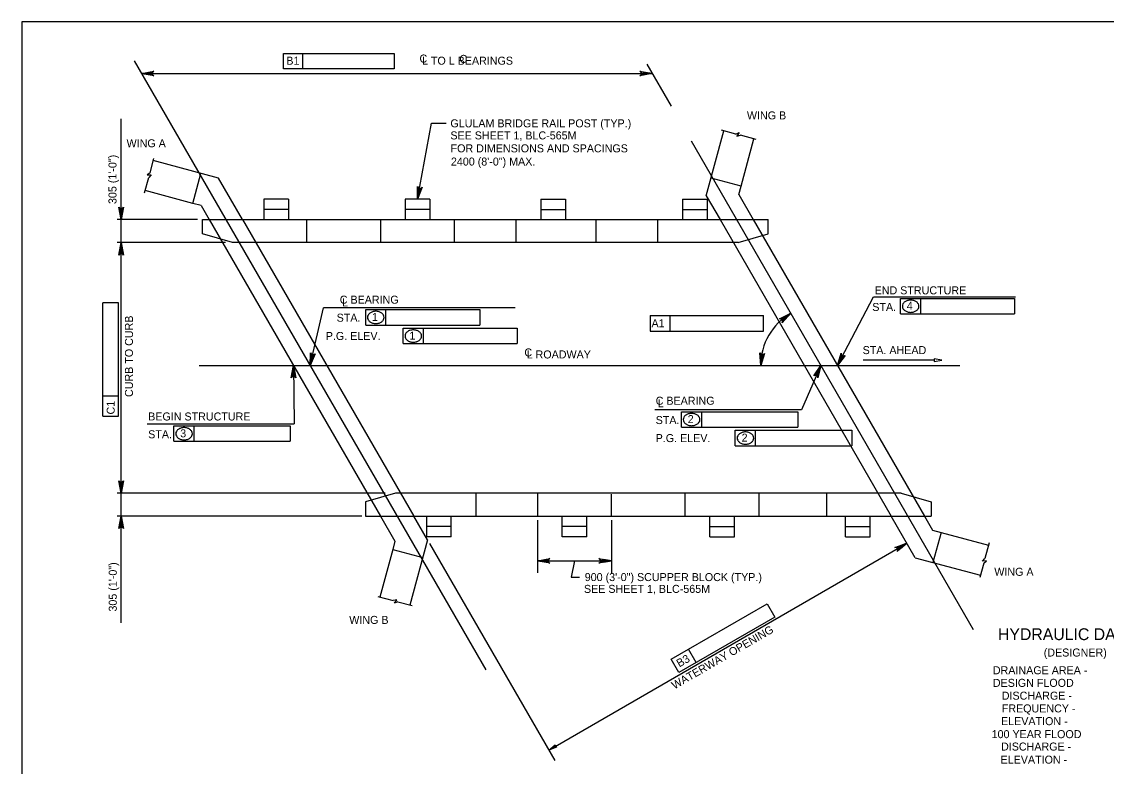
# Model space of a CAD drawing. Extents: x -8 to 75, y -110 to 0.
# Drawn here: x 1.75 to 18.01, y -55.91 to -44.75 of the extents above; entities that cross this region are included whole.
import ezdxf

# ---------------------------------------------------------------- set-up
doc = ezdxf.new("R2010")
doc.units = 0
for name, color, linetype in [('1', 7, 'Continuous'), ('2', 7, 'Continuous'), ('3', 7, 'Continuous'), ('4', 7, 'Continuous')]:
    doc.layers.add(name, color=color, linetype=linetype)

msp = doc.modelspace()

# ---------------------------------------------------------------- linework, layer by layer
at = {"layer": '1'}
msp.add_lwpolyline([(1.75, -65.25), (33.25, -65.25), (33.25, -44.75), (1.75, -44.75)], close=True, dxfattribs=at)
at = {"layer": '2'}
for p, q in [((12.012, -47.361), (12.274, -46.385)), ((12.533, -47.217), (12.723, -46.506)), ((4.699, -47.095), (3.723, -46.833)), ((4.314, -47.474), (4.435, -47.024)), ((5.059, -47.718), (4.699, -47.095)), ((12.533, -47.217), (12.083, -47.097)), ((4.314, -47.474), (3.602, -47.283)), ((12.499, -47.343), (12.533, -47.217)), ((5.747, -47.41), (5.378, -47.41)), ((5.378, -47.41), (5.378, -47.718)), ((5.747, -47.41), (5.747, -47.718)), ((7.869, -47.41), (7.5, -47.41)), ((7.5, -47.41), (7.5, -47.718)), ((7.869, -47.41), (7.869, -47.718)), ((9.531, -47.41), (9.9, -47.41)), ((9.531, -47.41), (9.531, -47.718)), ((9.9, -47.41), (9.9, -47.718)), ((11.654, -47.41), (12.023, -47.41)), ((11.654, -47.41), (11.654, -47.718)), ((12.012, -47.361), (12.218, -47.718)), ((12.023, -47.41), (12.023, -47.718)), ((12.499, -47.343), (12.715, -47.718)), ((4.44, -47.507), (4.314, -47.474)), ((4.44, -47.507), (4.561, -47.718)), ((4.461, -47.718), (12.938, -47.718)), ((4.461, -47.933), (4.461, -47.718)), ((4.561, -47.718), (7.129, -52.164)), ((5.059, -47.718), (7.626, -52.164)), ((12.218, -47.718), (14.785, -52.164)), ((12.715, -47.718), (15.282, -52.164)), ((12.938, -47.933), (12.938, -47.718)), ((4.908, -48.063), (4.461, -47.933)), ((12.49, -48.063), (12.938, -47.933)), ((12.49, -48.063), (4.908, -48.063)), ((7.351, -51.818), (6.904, -51.949)), ((14.933, -51.818), (7.351, -51.818)), ((14.933, -51.818), (15.381, -51.949)), ((6.904, -51.949), (6.904, -52.164)), ((15.381, -51.949), (15.381, -52.164)), ((6.904, -52.164), (15.381, -52.164)), ((7.129, -52.164), (7.345, -52.538)), ((7.832, -52.52), (7.626, -52.164)), ((7.821, -52.472), (7.821, -52.164)), ((8.19, -52.472), (8.19, -52.164)), ((9.851, -52.472), (9.851, -52.164)), ((10.22, -52.472), (10.22, -52.164)), ((12.067, -52.472), (12.067, -52.164)), ((12.436, -52.472), (12.436, -52.164)), ((14.097, -52.472), (14.097, -52.164)), ((14.466, -52.472), (14.466, -52.164)), ((15.145, -52.787), (14.785, -52.164)), ((15.282, -52.164), (15.404, -52.375)), ((8.19, -52.472), (7.821, -52.472)), ((10.22, -52.472), (9.851, -52.472)), ((12.067, -52.472), (12.436, -52.472)), ((14.097, -52.472), (14.466, -52.472)), ((15.404, -52.375), (15.53, -52.408)), ((15.53, -52.408), (15.409, -52.858)), ((15.53, -52.408), (16.241, -52.599)), ((7.311, -52.664), (7.12, -53.376)), ((7.345, -52.538), (7.311, -52.664)), ((7.311, -52.664), (7.761, -52.785)), ((7.832, -52.52), (7.57, -53.497)), ((15.145, -52.787), (16.121, -53.049))]:
    msp.add_line(p, q, dxfattribs=at)
at = {"layer": '3'}
for p, q in [((3.435, -45.336), (8.708, -54.47)), ((11.121, -45.387), (11.485, -46.018)), ((3.545, -45.527), (11.202, -45.527)), ((7.894, -46.272), (8.114, -46.272)), ((12.455, -46.434), (12.242, -46.377)), ((12.455, -46.434), (12.506, -46.413)), ((12.506, -46.413), (12.471, -46.465)), ((12.471, -46.465), (12.525, -46.453)), ((12.758, -46.515), (12.525, -46.453)), ((11.785, -46.537), (16.014, -53.863)), ((3.674, -47.015), (3.731, -46.801)), ((3.593, -47.318), (3.656, -47.084)), ((3.674, -47.015), (3.631, -47.048)), ((3.631, -47.048), (3.693, -47.044)), ((3.693, -47.044), (3.656, -47.084)), ((5.747, -47.564), (5.378, -47.564)), ((7.869, -47.564), (7.5, -47.564)), ((9.531, -47.564), (9.9, -47.564)), ((11.654, -47.564), (12.023, -47.564)), ((6.024, -48.063), (6.024, -47.718)), ((7.131, -48.063), (7.131, -47.718)), ((8.239, -48.063), (8.239, -47.718)), ((9.162, -48.063), (9.162, -47.718)), ((10.362, -48.063), (10.362, -47.718)), ((11.285, -48.063), (11.285, -47.718)), ((8.559, -51.818), (8.559, -52.164)), ((9.482, -51.818), (9.482, -52.164)), ((10.59, -52.164), (10.59, -51.835)), ((11.697, -52.164), (11.697, -51.818)), ((12.805, -52.164), (12.805, -51.818)), ((13.82, -52.164), (13.82, -51.818)), ((8.19, -52.318), (7.821, -52.318)), ((10.22, -52.318), (9.851, -52.318)), ((12.067, -52.318), (12.436, -52.318)), ((14.097, -52.318), (14.466, -52.318)), ((16.251, -52.564), (16.188, -52.798)), ((16.151, -52.838), (16.188, -52.798)), ((16.213, -52.834), (16.151, -52.838)), ((16.17, -52.867), (16.213, -52.834)), ((16.17, -52.867), (16.112, -53.081)), ((7.086, -53.367), (7.319, -53.429)), ((7.372, -53.417), (7.319, -53.429)), ((7.338, -53.469), (7.372, -53.417)), ((7.388, -53.448), (7.338, -53.469)), ((7.388, -53.448), (7.602, -53.505))]:
    msp.add_line(p, q, dxfattribs=at)
msp.add_lwpolyline([(3.663, -45.507), (3.663, -45.547), (3.545, -45.527)], close=True, dxfattribs=at)
at = {"layer": '4'}
for p, q in [((5.674, -45.225), (5.963, -45.225)), ((5.674, -45.456), (5.674, -45.225)), ((5.963, -45.456), (5.963, -45.225)), ((5.963, -45.225), (7.335, -45.225)), ((7.335, -45.225), (7.335, -45.456)), ((7.335, -45.456), (5.674, -45.456)), ((3.239, -53.763), (3.239, -46.209)), ((7.685, -47.41), (7.894, -46.272)), ((4.383, -47.718), (3.181, -47.718)), ((4.807, -48.063), (3.181, -48.063)), ((13.977, -49.903), (14.52, -48.874)), ((14.52, -48.874), (16.647, -48.874)), ((14.924, -48.899), (15.227, -48.899)), ((14.924, -49.129), (14.924, -48.899)), ((15.227, -49.129), (15.227, -48.899)), ((15.227, -48.899), (16.634, -48.899)), ((16.634, -48.899), (16.634, -49.129)), ((3.202, -48.965), (2.966, -48.965)), ((2.966, -50.363), (2.966, -48.965)), ((3.202, -50.666), (3.202, -48.965)), ((6.072, -49.903), (6.274, -49.042)), ((9.146, -49.042), (6.274, -49.042)), ((6.907, -49.067), (7.21, -49.067)), ((6.907, -49.298), (6.907, -49.067)), ((7.21, -49.298), (7.21, -49.067)), ((7.21, -49.067), (8.617, -49.067)), ((8.617, -49.067), (8.617, -49.298)), ((11.169, -49.154), (11.472, -49.154)), ((11.169, -49.154), (11.169, -49.39)), ((11.471, -49.39), (11.472, -49.154)), ((11.472, -49.154), (12.87, -49.154)), ((12.87, -49.39), (12.87, -49.154)), ((14.924, -49.129), (16.634, -49.129)), ((6.907, -49.298), (8.617, -49.298)), ((7.468, -49.346), (7.771, -49.346)), ((7.468, -49.576), (7.468, -49.346)), ((7.771, -49.576), (7.771, -49.346)), ((7.771, -49.346), (9.179, -49.346)), ((9.179, -49.346), (9.179, -49.576)), ((11.169, -49.39), (12.87, -49.39)), ((7.468, -49.576), (9.179, -49.576)), ((4.412, -49.903), (15.812, -49.903)), ((5.823, -49.903), (5.834, -50.78)), ((13.728, -49.903), (13.441, -50.567)), ((15.426, -49.825), (14.361, -49.825)), ((2.966, -50.665), (2.966, -50.363)), ((3.202, -50.363), (2.966, -50.363)), ((2.966, -50.665), (3.202, -50.666)), ((13.441, -50.567), (11.238, -50.567)), ((11.64, -50.597), (11.943, -50.597)), ((11.64, -50.828), (11.64, -50.597)), ((11.943, -50.828), (11.943, -50.597)), ((11.943, -50.597), (13.383, -50.597)), ((13.383, -50.597), (13.383, -50.828)), ((3.631, -50.78), (5.834, -50.78)), ((4.033, -51.041), (4.033, -50.81)), ((4.033, -50.81), (4.336, -50.81)), ((4.336, -51.041), (4.336, -50.81)), ((4.336, -50.81), (5.776, -50.81)), ((5.776, -50.81), (5.776, -51.041)), ((11.64, -50.828), (13.383, -50.828)), ((12.447, -51.107), (12.447, -50.876)), ((12.447, -50.876), (12.751, -50.876)), ((12.751, -51.107), (12.751, -50.876)), ((12.751, -50.876), (14.191, -50.876)), ((14.191, -50.876), (14.191, -51.107)), ((4.033, -51.041), (5.776, -51.041)), ((12.447, -51.107), (14.191, -51.107)), ((7.198, -51.818), (3.181, -51.818)), ((6.849, -52.164), (3.181, -52.164)), ((9.482, -52.226), (9.482, -53.011)), ((10.59, -52.226), (10.59, -53.011)), ((7.863, -52.575), (9.74, -55.825)), ((9.65, -55.67), (15.019, -52.57)), ((9.482, -52.834), (10.59, -52.834)), ((10.036, -52.834), (9.987, -53.08)), ((9.987, -53.08), (10.11, -53.08)), ((11.743, -54.159), (12.926, -53.478)), ((12.926, -53.478), (13.041, -53.678)), ((13.041, -53.678), (11.602, -54.507)), ((11.487, -54.307), (11.743, -54.159)), ((11.858, -54.359), (11.743, -54.159)), ((11.602, -54.507), (11.487, -54.307))]:
    msp.add_line(p, q, dxfattribs=at)
for points in [[(3.545, -45.527), (3.732, -45.492), (3.717, -45.502), (3.71, -45.515), (3.708, -45.527), (3.71, -45.54), (3.717, -45.552), (3.732, -45.562), (3.545, -45.527), (3.717, -45.552), (3.71, -45.54), (3.545, -45.527), (3.708, -45.527), (3.71, -45.515), (3.545, -45.527), (3.717, -45.502)], [(11.202, -45.527), (11.015, -45.562), (11.03, -45.552), (11.037, -45.54), (11.039, -45.527), (11.037, -45.515), (11.03, -45.502), (11.015, -45.492), (11.202, -45.527), (11.03, -45.502), (11.037, -45.515), (11.202, -45.527), (11.039, -45.527), (11.037, -45.54), (11.202, -45.527), (11.03, -45.552)], [(7.685, -47.41), (7.684, -47.22), (7.691, -47.236), (7.702, -47.246), (7.714, -47.25), (7.727, -47.25), (7.74, -47.245), (7.753, -47.233), (7.685, -47.41), (7.74, -47.245), (7.727, -47.25), (7.685, -47.41), (7.714, -47.25), (7.702, -47.246), (7.685, -47.41), (7.691, -47.236)], [(3.239, -47.718), (3.204, -47.531), (3.214, -47.545), (3.226, -47.553), (3.239, -47.555), (3.251, -47.553), (3.264, -47.545), (3.274, -47.531), (3.239, -47.718), (3.264, -47.545), (3.251, -47.553), (3.239, -47.718), (3.239, -47.555), (3.226, -47.553), (3.239, -47.718), (3.214, -47.545)], [(3.239, -48.063), (3.274, -48.25), (3.264, -48.236), (3.251, -48.228), (3.239, -48.226), (3.226, -48.228), (3.214, -48.236), (3.204, -48.25), (3.239, -48.063), (3.214, -48.236), (3.226, -48.228), (3.239, -48.063), (3.239, -48.226), (3.251, -48.228), (3.239, -48.063), (3.264, -48.236)], [(13.277, -49.122), (13.15, -49.263), (13.156, -49.246), (13.154, -49.232), (13.148, -49.221), (13.139, -49.212), (13.125, -49.207), (13.108, -49.207), (13.277, -49.122), (13.125, -49.207), (13.139, -49.212), (13.277, -49.122), (13.148, -49.221), (13.154, -49.232), (13.277, -49.122), (13.156, -49.246)], [(6.072, -49.903), (6.08, -49.713), (6.087, -49.73), (6.097, -49.74), (6.109, -49.745), (6.122, -49.745), (6.135, -49.741), (6.148, -49.729), (6.072, -49.903), (6.135, -49.741), (6.122, -49.745), (6.072, -49.903), (6.109, -49.745), (6.097, -49.74), (6.072, -49.903), (6.087, -49.73)], [(12.827, -49.903), (12.815, -49.714), (12.823, -49.73), (12.834, -49.738), (12.846, -49.742), (12.859, -49.741), (12.872, -49.736), (12.884, -49.723), (12.827, -49.903), (12.872, -49.736), (12.859, -49.741), (12.827, -49.903), (12.846, -49.742), (12.834, -49.738), (12.827, -49.903), (12.823, -49.73)], [(13.977, -49.903), (14.033, -49.722), (14.035, -49.739), (14.042, -49.751), (14.053, -49.759), (14.065, -49.763), (14.079, -49.762), (14.095, -49.754), (13.977, -49.903), (14.079, -49.762), (14.065, -49.763), (13.977, -49.903), (14.053, -49.759), (14.042, -49.751), (13.977, -49.903), (14.035, -49.739)], [(5.823, -49.903), (5.86, -50.089), (5.85, -50.075), (5.838, -50.067), (5.825, -50.065), (5.813, -50.067), (5.8, -50.075), (5.79, -50.09), (5.823, -49.903), (5.8, -50.075), (5.813, -50.067), (5.823, -49.903), (5.825, -50.065), (5.838, -50.067), (5.823, -49.903), (5.85, -50.075)], [(13.728, -49.903), (13.686, -50.088), (13.683, -50.071), (13.674, -50.059), (13.663, -50.052), (13.651, -50.049), (13.637, -50.051), (13.622, -50.06), (13.728, -49.903), (13.637, -50.051), (13.651, -50.049), (13.728, -49.903), (13.663, -50.052), (13.674, -50.059), (13.728, -49.903), (13.683, -50.071)], [(3.239, -51.818), (3.204, -51.632), (3.214, -51.646), (3.226, -51.654), (3.239, -51.656), (3.251, -51.654), (3.264, -51.646), (3.274, -51.632), (3.239, -51.818), (3.264, -51.646), (3.251, -51.654), (3.239, -51.818), (3.239, -51.656), (3.226, -51.654), (3.239, -51.818), (3.214, -51.646)], [(3.239, -52.164), (3.274, -52.351), (3.264, -52.337), (3.251, -52.329), (3.239, -52.327), (3.226, -52.329), (3.214, -52.337), (3.204, -52.351), (3.239, -52.164), (3.214, -52.337), (3.226, -52.329), (3.239, -52.164), (3.239, -52.327), (3.251, -52.329), (3.239, -52.164), (3.264, -52.337)], [(15.019, -52.57), (14.875, -52.693), (14.883, -52.677), (14.883, -52.663), (14.878, -52.651), (14.87, -52.641), (14.858, -52.634), (14.84, -52.633), (15.019, -52.57), (14.858, -52.634), (14.87, -52.641), (15.019, -52.57), (14.878, -52.651), (14.883, -52.663), (15.019, -52.57), (14.883, -52.677)], [(9.482, -52.834), (9.668, -52.799), (9.654, -52.809), (9.646, -52.822), (9.644, -52.834), (9.646, -52.847), (9.654, -52.859), (9.668, -52.869), (9.482, -52.834), (9.654, -52.859), (9.646, -52.847), (9.482, -52.834), (9.644, -52.834), (9.646, -52.822), (9.482, -52.834), (9.654, -52.809)], [(10.59, -52.834), (10.403, -52.869), (10.418, -52.859), (10.425, -52.847), (10.427, -52.834), (10.425, -52.822), (10.418, -52.809), (10.403, -52.799), (10.59, -52.834), (10.418, -52.809), (10.425, -52.822), (10.59, -52.834), (10.427, -52.834), (10.425, -52.847), (10.59, -52.834), (10.418, -52.859)]]:
    msp.add_lwpolyline(points, dxfattribs=at)
for points in [[(7.687, -47.29), (7.726, -47.297), (7.685, -47.41)], [(3.219, -47.602), (3.258, -47.602), (3.239, -47.718)], [(3.219, -48.179), (3.258, -48.179), (3.239, -48.063)], [(13.699, -50.019), (13.663, -50.003), (13.728, -49.903)], [(15.426, -49.806), (15.426, -49.845), (15.541, -49.825)], [(3.219, -51.703), (3.258, -51.703), (3.239, -51.818)], [(3.219, -52.28), (3.258, -52.28), (3.239, -52.164)], [(14.905, -52.612), (14.925, -52.647), (15.019, -52.57)], [(9.6, -52.814), (9.6, -52.854), (9.482, -52.834)], [(10.472, -52.814), (10.472, -52.854), (10.59, -52.834)], [(9.744, -55.592), (9.764, -55.627), (9.65, -55.67)]]:
    msp.add_lwpolyline(points, close=True, dxfattribs=at)
for centre, radius, start, end in [((15.064, -49.055), 0.129, 106.9552, 126.3544), ((15.075, -49.093), 0.169, 90, 106.9552), ((15.075, -49.093), 0.169, 73.0448, 90), ((15.087, -49.055), 0.129, 53.6456, 73.0448), ((7.058, -49.261), 0.169, 90, 106.9552), ((7.058, -49.261), 0.169, 73.0448, 90), ((15.019, -49.016), 0.0684, 150.6308, 180), ((15.019, -49.016), 0.0684, 180, 209.3692), ((15.046, -49.031), 0.0995, 126.3544, 150.6308), ((15.046, -49.001), 0.0995, 209.3692, 233.6456), ((15.064, -48.977), 0.129, 233.6456, 253.0448), ((15.087, -48.977), 0.129, 286.9552, 306.3544), ((15.104, -49.031), 0.0995, 29.3692, 53.6456), ((15.104, -49.001), 0.0995, 306.3544, 330.6308), ((15.131, -49.016), 0.0684, 0, 29.3692), ((15.131, -49.016), 0.0684, 330.6308, 0), ((7.002, -49.184), 0.0684, 150.6308, 180), ((7.002, -49.184), 0.0684, 180, 209.3692), ((7.029, -49.199), 0.0995, 126.3544, 150.6308), ((7.029, -49.169), 0.0995, 209.3692, 233.6456), ((7.047, -49.223), 0.129, 106.9552, 126.3544), ((7.047, -49.145), 0.129, 233.6456, 253.0448), ((7.07, -49.223), 0.129, 53.6456, 73.0448), ((7.07, -49.145), 0.129, 286.9552, 306.3544), ((7.087, -49.199), 0.0995, 29.3692, 53.6456), ((7.087, -49.169), 0.0995, 306.3544, 330.6308), ((7.114, -49.184), 0.0684, 0, 29.3692), ((7.114, -49.184), 0.0684, 330.6308, 0), ((13.728, -49.903), 0.901, 119.9992, 179.9979), ((15.075, -48.939), 0.169, 253.0448, 270), ((15.075, -48.939), 0.169, 270, 286.9552), ((7.058, -49.107), 0.169, 253.0448, 270), ((7.058, -49.107), 0.169, 270, 286.9552), ((7.591, -49.478), 0.0995, 126.3544, 150.6308), ((7.608, -49.502), 0.129, 106.9552, 126.3544), ((7.62, -49.54), 0.169, 90, 106.9552), ((7.62, -49.54), 0.169, 73.0448, 90), ((7.631, -49.502), 0.129, 53.6456, 73.0448), ((7.649, -49.478), 0.0995, 29.3692, 53.6456), ((7.564, -49.463), 0.0684, 150.6308, 180), ((7.564, -49.463), 0.0684, 180, 209.3692), ((7.591, -49.448), 0.0995, 209.3692, 233.6456), ((7.608, -49.424), 0.129, 233.6456, 253.0448), ((7.62, -49.386), 0.169, 253.0448, 270), ((7.62, -49.386), 0.169, 270, 286.9552), ((7.631, -49.424), 0.129, 286.9552, 306.3544), ((7.649, -49.448), 0.0995, 306.3544, 330.6308), ((7.676, -49.463), 0.0684, 0, 29.3692), ((7.676, -49.463), 0.0684, 330.6308, 0), ((11.735, -50.715), 0.0684, 150.6308, 180), ((11.735, -50.715), 0.0684, 180, 209.3692), ((11.762, -50.73), 0.0995, 126.3544, 150.6308), ((11.78, -50.754), 0.129, 106.9552, 126.3544), ((11.791, -50.792), 0.169, 90, 106.9552), ((11.791, -50.792), 0.169, 73.0448, 90), ((11.803, -50.754), 0.129, 53.6456, 73.0448), ((11.821, -50.73), 0.0995, 29.3692, 53.6456), ((11.848, -50.715), 0.0684, 0, 29.3692), ((11.848, -50.715), 0.0684, 330.6308, 0), ((4.155, -50.943), 0.0995, 126.3544, 150.6308), ((4.173, -50.967), 0.129, 106.9552, 126.3544), ((4.184, -51.005), 0.169, 90, 106.9552), ((4.184, -51.005), 0.169, 73.0448, 90), ((4.196, -50.967), 0.129, 53.6456, 73.0448), ((4.213, -50.943), 0.0995, 29.3692, 53.6456), ((11.762, -50.699), 0.0995, 209.3692, 233.6456), ((11.78, -50.675), 0.129, 233.6456, 253.0448), ((11.791, -50.638), 0.169, 253.0448, 270), ((11.791, -50.638), 0.169, 270, 286.9552), ((11.803, -50.675), 0.129, 286.9552, 306.3544), ((11.821, -50.699), 0.0995, 306.3544, 330.6308), ((4.128, -50.928), 0.0684, 150.6308, 180), ((4.128, -50.928), 0.0684, 180, 209.3692), ((4.155, -50.912), 0.0995, 209.3692, 233.6456), ((4.173, -50.889), 0.129, 233.6456, 253.0448), ((4.184, -50.851), 0.169, 253.0448, 270), ((4.184, -50.851), 0.169, 270, 286.9552), ((4.196, -50.889), 0.129, 286.9552, 306.3544), ((4.213, -50.912), 0.0995, 306.3544, 330.6308), ((4.24, -50.928), 0.0684, 0, 29.3692), ((4.24, -50.928), 0.0684, 330.6308, 0), ((12.543, -50.993), 0.0684, 150.6308, 180), ((12.543, -50.993), 0.0684, 180, 209.3692), ((12.57, -51.009), 0.0995, 126.3544, 150.6308), ((12.57, -50.978), 0.0995, 209.3692, 233.6456), ((12.587, -51.033), 0.129, 106.9552, 126.3544), ((12.599, -51.07), 0.169, 90, 106.9552), ((12.599, -51.07), 0.169, 73.0448, 90), ((12.61, -51.033), 0.129, 53.6456, 73.0448), ((12.628, -51.009), 0.0995, 29.3692, 53.6456), ((12.628, -50.978), 0.0995, 306.3544, 330.6308), ((12.655, -50.993), 0.0684, 0, 29.3692), ((12.655, -50.993), 0.0684, 330.6308, 0), ((12.587, -50.954), 0.129, 233.6456, 253.0448), ((12.599, -50.916), 0.169, 253.0448, 270), ((12.599, -50.916), 0.169, 270, 286.9552), ((12.61, -50.954), 0.129, 286.9552, 306.3544)]:
    msp.add_arc(centre, radius, start, end, dxfattribs=at)

# ---------------------------------------------------------------- texts
for s, height, p in [('B1', 0.12, (5.717, -45.395)), ('C', 0.12, (7.713, -45.363)), ('L TO L BEARINGS', 0.12, (7.75, -45.395)), ('C', 0.12, (8.312, -45.368)), ('WING B', 0.12, (12.621, -46.215)), ('GLULAM BRIDGE RAIL POST (TYP.)', 0.12, (8.176, -46.334)), ('SEE SHEET 1, BLC-565M', 0.12, (8.176, -46.515)), ('WING A', 0.12, (3.322, -46.633)), ('FOR DIMENSIONS AND SPACINGS', 0.12, (8.179, -46.709)), ('2400 (8\'-0") MAX.', 0.12, (8.184, -46.907)), ('END STRUCTURE', 0.12, (14.535, -48.838)), ('C BEARING', 0.12, (6.518, -48.978)), ('L', 0.12, (6.551, -49.02)), ('STA.', 0.12, (14.5, -49.087)), ('4', 0.12, (15.017, -49.07)), ('STA.', 0.12, (6.471, -49.248)), ('1', 0.12, (7, -49.238)), ('P.G. ELEV.', 0.12, (6.308, -49.522)), ('1', 0.12, (7.562, -49.517)), ('C', 0.12, (9.285, -49.769)), ('L ROADWAY', 0.12, (9.319, -49.799)), ('STA. AHEAD', 0.12, (14.355, -49.734)), ('C BEARING', 0.12, (11.253, -50.493)), ('L', 0.12, (11.286, -50.53)), ('BEGIN STRUCTURE', 0.12, (3.646, -50.729)), ('STA.', 0.12, (11.253, -50.783)), ('2', 0.12, (11.733, -50.769)), ('STA.', 0.12, (3.646, -50.996)), ('3', 0.12, (4.126, -50.982)), ('P.G. ELEV.', 0.12, (11.253, -51.053)), ('2', 0.12, (12.541, -51.047)), ('WING A', 0.12, (16.329, -53.058)), ('900 (3\'-0") SCUPPER BLOCK (TYP.)', 0.12, (10.19, -53.137)), ('SEE SHEET 1, BLC-565M', 0.12, (10.178, -53.314)), ('WING B', 0.12, (6.66, -53.779)), ('HYDRAULIC DATA', 0.17717, (16.384, -54.022)), ('(DESIGNER)', 0.12, (17.07, -54.268)), ('DRAINAGE AREA - ', 0.12, (16.307, -54.534)), ('DESIGN FLOOD  ', 0.12, (16.307, -54.723)), ('   DISCHARGE - ', 0.12, (16.307, -54.915)), ('   FREQUENCY - ', 0.12, (16.307, -55.106)), ('   ELEVATION - ', 0.12, (16.296, -55.297)), ('100 YEAR FLOOD', 0.12, (16.289, -55.492)), ('   DISCHARGE - ', 0.12, (16.296, -55.678)), ('   ELEVATION - ', 0.12, (16.289, -55.874))]:
    msp.add_text(s, height=height, dxfattribs=at).set_placement(p)
for s, rotation, p in [('305 (1\'-0")', 90, (3.171, -47.484)), ('CURB TO CURB', 90, (3.418, -50.377)), ('A1', 359.9382, (11.19, -49.332)), ('C1', 89.9382, (3.144, -50.639)), ('305 (1\'-0")', 90, (3.175, -53.594)), ('WATERWAY OPENING', 30, (11.535, -54.763)), ('B3', 29.9438, (11.608, -54.433))]:
    msp.add_text(s, height=0.12, rotation=rotation, dxfattribs=at).set_placement(p)

doc.saveas('drawing.dxf')
